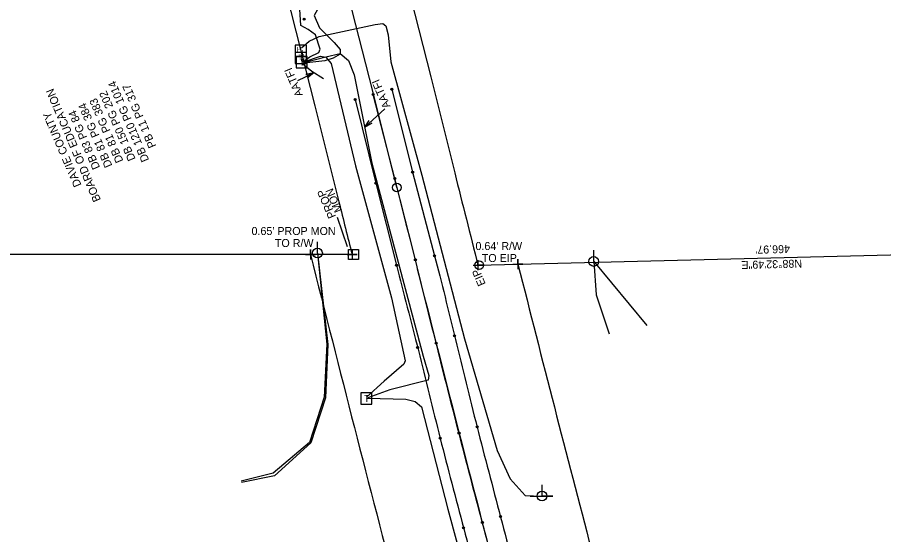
# Model space of a CAD drawing. Extents: x 1550153 to 1552579, y 809637 to 812160.
# Drawn here: x 1551459.6 to 1551894.8, y 811136.9 to 811396.7 of the extents above; entities that cross this region are included whole.
import ezdxf

# ---------------------------------------------------------------- set-up
doc = ezdxf.new("R2010")
doc.units = 0
for name, color, linetype in [('Default', 7, 'Continuous'), ('E_NCDOT_Horizontal_Alignment', 7, 'Continuous'), ('E_NCDOT_Horizontal_Alignment_Curve', 7, 'Continuous'), ('E_NCDOT_Horizontal_Alignment_Tick_Label', 7, 'Continuous'), ('Exist DTM Crownline', 7, 'Continuous'), ('Exist Property Corner CELL', 7, 'Continuous'), ('Exist Property Iron Pin CELL', 7, 'Continuous'), ('Exist Property Iron Pin Text', 7, 'Continuous'), ('Exist Property Line', 7, 'Continuous'), ('Exist Property Line Text', 7, 'Continuous'), ('Exist Property Monument CELL', 7, 'Continuous'), ('Exist Property Monument Leader', 7, 'Continuous'), ('Exist Property Monument Text', 7, 'Continuous'), ('Exist Property Text', 7, 'Continuous'), ('Exist Right of Way Line', 7, 'Continuous'), ('Exist Roads EOP', 7, 'Continuous'), ('Exist Utilities Power Joint Use Telephone CELL', 7, 'Continuous'), ('Exist Utilities Power Pole CELL', 7, 'Continuous'), ('Exist Utilities Power UG Cable SUE LOS B', 7, 'Continuous'), ('Exist Utilities Telephone Hand Hole CELL', 7, 'Continuous'), ('Exist Utilities Telephone Pedestal CELL', 7, 'Continuous'), ('Exist Utilities Telephone Text', 7, 'Continuous'), ('Exist Utilities Telephone UG Cable SUE LOS B', 7, 'Continuous'), ('Exist Utilities Telephone UG FO SUE LOS B', 7, 'Continuous')]:
    doc.layers.add(name, color=color, linetype=linetype)

# ---------------------------------------------------------------- blocks, each defined once
blk = doc.blocks.new('SurveyPointCell')
at = {"layer": 'Default'}
for p, q in [((-0.5, 0), (0.5, 0)), ((0, -0.5), (0, 0.5))]:
    blk.add_line(p, q, dxfattribs=at)
blk.add_circle((0, 0), 0.5, dxfattribs=at)

msp = doc.modelspace()

# ---------------------------------------------------------------- linework, layer by layer
at = {"layer": 'Default'}
msp.add_line((1551650.26, 811311.28), (1551638.16, 811359.58), dxfattribs=at)
msp.add_line((1551650.26, 811311.28), (1551638.16, 811359.58), dxfattribs=at)
msp.add_line((1551650.26, 811311.28), (1551638.16, 811359.58), dxfattribs=at)
at = {"layer": 'E_NCDOT_Horizontal_Alignment'}
for p, q in [((1551638.16, 811359.58), (1551604.47, 811492.11)), ((1551650.26, 811311.28), (1551638.16, 811359.58))]:
    msp.add_line(p, q, dxfattribs=at)
for radius in [2.2, 0.0707]:
    msp.add_circle((1551650.26, 811311.28), radius, dxfattribs=at)
at = {"layer": 'E_NCDOT_Horizontal_Alignment_Curve'}
msp.add_arc((1571051.3, 816169.19), 20000, 194.057496, 194.632887, dxfattribs=at)
msp.add_arc((1571051.3, 816169.19), 20000, 194.057496, 194.632887, dxfattribs=at)
at = {"layer": 'E_NCDOT_Horizontal_Alignment_Tick_Label'}
msp.add_line((1551650.26, 811311.28), (1551638.16, 811359.58), dxfattribs=at)
at = {"layer": 'Exist DTM Crownline'}
for p, q in [((1551649.24, 811315.83), (1551638.36, 811358.03)), ((1551649.24, 811315.83), (1551638.36, 811358.03)), ((1551659.56, 811274.89), (1551649.24, 811315.83)), ((1551659.56, 811274.89), (1551649.24, 811315.83))]:
    msp.add_line(p, q, dxfattribs=at)
msp.add_open_spline([(1551774.27, 810871.88), (1551769.96, 810884.28), (1551760.75, 810912.22), (1551745.66, 810955.91), (1551731.5, 811003.54), (1551718, 811050.78), (1551705.43, 811097.26), (1551693.24, 811142.67), (1551681.43, 811187.98), (1551670.2, 811231.95), (1551663.06, 811260.98), (1551659.56, 811274.89)], degree=3, dxfattribs=at)
msp.add_open_spline([(1551774.27, 810871.88), (1551769.96, 810884.28), (1551760.75, 810912.22), (1551745.66, 810955.91), (1551731.5, 811003.54), (1551718, 811050.78), (1551705.43, 811097.26), (1551693.24, 811142.67), (1551681.43, 811187.98), (1551670.2, 811231.95), (1551663.06, 811260.98), (1551659.56, 811274.89)], degree=3, dxfattribs=at)
at = {"layer": 'Exist Property Corner CELL'}
for p, q in [((1551606.86, 811277.65), (1551606.86, 811277.65)), ((1551627.77, 811277.65), (1551627.77, 811277.65)), ((1551691.02, 811272.23), (1551691.02, 811272.23)), ((1551711.09, 811272.74), (1551711.09, 811272.74))]:
    msp.add_line(p, q, dxfattribs=at)
for points in [[(1551604.36, 811277.65), (1551609.36, 811277.65), (1551606.86, 811277.65), (1551606.86, 811280.15), (1551606.86, 811275.15)], [(1551625.27, 811277.65), (1551630.27, 811277.65), (1551627.77, 811277.65), (1551627.77, 811280.15), (1551627.77, 811275.15)], [(1551688.52, 811272.23), (1551693.52, 811272.23), (1551691.02, 811272.23), (1551691.02, 811274.73), (1551691.02, 811269.73)], [(1551708.59, 811272.74), (1551713.59, 811272.74), (1551711.09, 811272.74), (1551711.09, 811275.24), (1551711.09, 811270.24)]]:
    msp.add_lwpolyline(points, dxfattribs=at)
at = {"layer": 'Exist Property Iron Pin CELL'}
for radius in [2.2, 2.2, 0.0707, 0.0707]:
    msp.add_circle((1551691.66, 811272.25), radius, dxfattribs=at)
at = {"layer": 'Exist Property Line'}
for p, q in [((1551711.09, 811272.74), (1552177.91, 811284.58)), ((1551606.86, 811277.65), (1550155.29, 811277.65))]:
    msp.add_line(p, q, dxfattribs=at)
at = {"layer": 'Exist Property Monument CELL'}
msp.add_line((1551628.41, 811277.65), (1551628.41, 811277.65), dxfattribs=at)
msp.add_line((1551628.41, 811277.65), (1551628.41, 811277.65), dxfattribs=at)
msp.add_lwpolyline([(1551625.92, 811275.16), (1551625.92, 811280.15), (1551630.91, 811280.15), (1551630.91, 811275.16), (1551625.92, 811275.16)], dxfattribs=at)
msp.add_lwpolyline([(1551625.92, 811275.16), (1551625.92, 811280.15), (1551630.91, 811280.15), (1551630.91, 811275.16), (1551625.92, 811275.16)], dxfattribs=at)
at = {"layer": 'Exist Property Monument Leader'}
msp.add_line((1551625.48, 811281.54), (1551620.36, 811296.19), dxfattribs=at)
at = {"layer": 'Exist Right of Way Line'}
for p, q in [((1551627.77, 811277.65), (1551606.86, 811277.65)), ((1551691.02, 811272.23), (1551711.09, 811272.74))]:
    msp.add_line(p, q, dxfattribs=at)
for points in [[(1551633.36, 811500.25), (1551633.56, 811499.43), (1551667.25, 811366.92), (1551679.36, 811318.56)], [(1551575.15, 811485.71), (1551575.38, 811484.78), (1551609.07, 811352.24), (1551621.15, 811303.99)]]:
    msp.add_lwpolyline(points, dxfattribs=at)
for centre, radius, start, end in [((1571051.3, 816169.19), 19970, 194.057496, 194.194571), ((1571051.3, 816169.19), 20030, 194.057496, 194.135176), ((1571051.08, 816168.98), 20050, 194.120183, 194.632887), ((1571050.91, 816169.06), 19950, 194.207218, 194.632275)]:
    msp.add_arc(centre, radius, start, end, dxfattribs=at)
at = {"layer": 'Exist Roads EOP'}
for p, q in [((1551647.8, 811360.59), (1551658.19, 811318.94)), ((1551647.8, 811360.59), (1551658.19, 811318.94)), ((1551629.3, 811355.5), (1551639.73, 811313.5)), ((1551629.3, 811355.5), (1551639.73, 811313.5)), ((1551658.19, 811318.94), (1551669.23, 811277)), ((1551658.19, 811318.94), (1551669.23, 811277)), ((1551639.73, 811313.5), (1551650.09, 811272.18)), ((1551639.73, 811313.5), (1551650.09, 811272.18))]:
    msp.add_line(p, q, dxfattribs=at)
for points in [[(1551669.23, 811277), (1551672.74, 811263.65), (1551679.61, 811234.96), (1551690.37, 811191.22), (1551702.41, 811145.66), (1551714.33, 811100.03), (1551727, 811053.46), (1551740.47, 811006.5), (1551755.13, 810959.34), (1551769.1, 810915.85), (1551778.93, 810888.33), (1551783.17, 810876.09)], [(1551669.23, 811277), (1551672.74, 811263.65), (1551679.61, 811234.96), (1551690.37, 811191.22), (1551702.41, 811145.66), (1551714.33, 811100.03), (1551727, 811053.46), (1551740.47, 811006.5), (1551755.13, 810959.34), (1551769.1, 810915.85), (1551778.93, 810888.33), (1551783.17, 810876.09)], [(1551650.09, 811272.18), (1551653.54, 811258.38), (1551661.25, 811229.54), (1551671.78, 811185.41), (1551683.85, 811140.03), (1551696.07, 811094.57), (1551708.62, 811047.91), (1551722.36, 811000.57), (1551736.98, 810952.93), (1551751.55, 810908.96), (1551760.88, 810880.93), (1551765.29, 810868.44)], [(1551650.09, 811272.18), (1551653.54, 811258.38), (1551661.25, 811229.54), (1551671.78, 811185.41), (1551683.85, 811140.03), (1551696.07, 811094.57), (1551708.62, 811047.91), (1551722.36, 811000.57), (1551736.98, 810952.93), (1551751.55, 810908.96), (1551760.88, 810880.93), (1551765.29, 810868.44)]]:
    msp.add_open_spline(points, degree=3, dxfattribs=at)
at = {"layer": 'Exist Utilities Power Joint Use Telephone CELL'}
msp.add_line((1551723.19, 811156.28), (1551723.19, 811156.28), dxfattribs=at)
msp.add_lwpolyline([(1551717.25, 811156.28), (1551728.59, 811156.24), (1551723.19, 811156.26), (1551723.19, 811161.9)], dxfattribs=at)
msp.add_circle((1551723.19, 811156.28), 2.45, dxfattribs=at)
at = {"layer": 'Exist Utilities Power Pole CELL'}
for p, q in [((1551610.39, 811278.35), (1551610.39, 811283.97)), ((1551749.18, 811274.1), (1551749.18, 811279.72)), ((1551610.39, 811278.35), (1551610.39, 811278.35)), ((1551749.18, 811274.1), (1551749.18, 811274.1))]:
    msp.add_line(p, q, dxfattribs=at)
for centre in [(1551610.39, 811278.35), (1551749.18, 811274.1)]:
    msp.add_circle(centre, 2.45, dxfattribs=at)
at = {"layer": 'Exist Utilities Power UG Cable SUE LOS B'}
for points in [[(1551610.38, 811278.35), (1551615.03, 811232.52), (1551613.73, 811205.91), (1551606.36, 811183.25), (1551588.07, 811167.69), (1551572.1, 811163.7)], [(1551610.39, 811278.35), (1551615.66, 811232.45), (1551614.45, 811205.63), (1551606.97, 811182.99), (1551588.76, 811166.39), (1551572.29, 811163.07)], [(1551749.17, 811274.1), (1551750.46, 811257.3), (1551756.99, 811237.84)], [(1551749.17, 811274.1), (1551775.84, 811242.01)]]:
    msp.add_lwpolyline(points, dxfattribs=at)
at = {"layer": 'Exist Utilities Telephone Hand Hole CELL'}
for p, q in [((1551599.19, 811382.74), (1551599.19, 811377.02)), ((1551604.92, 811382.74), (1551599.19, 811382.74)), ((1551602.05, 811379.88), (1551602.05, 811379.88)), ((1551604.92, 811377.02), (1551604.92, 811382.74)), ((1551599.19, 811377.02), (1551604.92, 811377.02))]:
    msp.add_line(p, q, dxfattribs=at)
at = {"layer": 'Exist Utilities Telephone Pedestal CELL'}
for p, q in [((1551601.97, 811376.33), (1551601.97, 811376.33)), ((1551602.39, 811374.26), (1551602.39, 811374.26)), ((1551634.9, 811205.29), (1551634.9, 811205.29))]:
    msp.add_line(p, q, dxfattribs=at)
for points in [[(1551599.25, 811373.5), (1551604.84, 811373.5), (1551604.84, 811379.09), (1551599.25, 811379.09), (1551599.25, 811373.5)], [(1551599.66, 811371.43), (1551605.26, 811371.43), (1551605.26, 811377.02), (1551599.66, 811377.02), (1551599.66, 811371.43)], [(1551632.17, 811202.47), (1551637.77, 811202.47), (1551637.77, 811208.06), (1551632.17, 811208.06), (1551632.17, 811202.47)]]:
    msp.add_lwpolyline(points, dxfattribs=at)
at = {"layer": 'Exist Utilities Telephone Text'}
for points in [[(1551600.52, 811365.04), (1551608.6, 811368.93), (1551604.54, 811368.09), (1551608.6, 811368.93), (1551605.41, 811366.28)], [(1551644.21, 811350.79), (1551634.13, 811341.55), (1551637.77, 811343.52), (1551634.13, 811341.55), (1551636.41, 811345)]]:
    msp.add_lwpolyline(points, dxfattribs=at)
at = {"layer": 'Exist Utilities Telephone UG Cable SUE LOS B'}
for points in [[(1551545.22, 811706.56), (1551568.37, 811609.79), (1551588, 811531.44), (1551606.27, 811452.93), (1551615.14, 811412.25), (1551613.21, 811406), (1551608.7, 811397.66), (1551611.45, 811391.52), (1551618.85, 811384.02), (1551621.83, 811380.6), (1551621.74, 811378.31), (1551618.28, 811376.25), (1551614.11, 811374.91), (1551603.55, 811373.65)], [(1551603.05, 811374.46), (1551606.52, 811376.87), (1551611, 811379.06), (1551611.78, 811380.7), (1551609.42, 811387.99), (1551605.7, 811390.64), (1551602.03, 811392.68), (1551601.58, 811400.81), (1551604.98, 811407.57), (1551605.14, 811413.37), (1551601.39, 811432.74), (1551598.88, 811434.08), (1551590.03, 811432.32)], [(1551603.47, 811374.33), (1551611.96, 811377.17), (1551614.58, 811376.75), (1551617.19, 811373.56), (1551629.5, 811322.12), (1551647.52, 811255.85), (1551654.41, 811224.24), (1551653.81, 811222.52), (1551643.81, 811214.04), (1551635.05, 811206.01)], [(1551603.59, 811374), (1551614.59, 811376.88), (1551621.72, 811378.56), (1551626.04, 811375.1), (1551628.85, 811367.88), (1551637.74, 811323.5), (1551663.4, 811226.58), (1551666.26, 811216.87), (1551665.95, 811214.46), (1551646.79, 811209.62), (1551635.64, 811205.53)], [(1551603.04, 811373.31), (1551607.52, 811369.75), (1551613.4, 811365.98)], [(1551635.47, 811205.41), (1551654.84, 811204.95), (1551659.43, 811203.7), (1551662.57, 811201.11), (1551675.9, 811149.68), (1551694.16, 811082.62), (1551715.46, 811009.19), (1551741.91, 810920.73), (1551757.61, 810876.2), (1551761.94, 810865.34), (1551769.04, 810860.85), (1551770.5, 810856.61)]]:
    msp.add_lwpolyline(points, dxfattribs=at)
at = {"layer": 'Exist Utilities Telephone UG FO SUE LOS B'}
for points in [[(1551602.44, 811381.48), (1551606.27, 811384.82), (1551611.26, 811387.07), (1551639.37, 811393.13), (1551643.29, 811393.6), (1551644.68, 811392.39), (1551645.96, 811387.93), (1551647.24, 811374.44), (1551662.83, 811317.5), (1551684.32, 811235.29), (1551700.68, 811179.2), (1551707.25, 811164.99), (1551714.69, 811156.53), (1551723.19, 811156.29)], [(1551603.14, 811378.1), (1551602.92, 811377.03), (1551602.58, 811376.35)]]:
    msp.add_lwpolyline(points, dxfattribs=at)

# ---------------------------------------------------------------- block references
at = {"layer": 'Default'}
for p in [(1551603.73, 811395.76), (1551603.73, 811395.76), (1551638.36, 811358.03), (1551638.36, 811358.03), (1551647.8, 811360.59), (1551647.8, 811360.59), (1551629.3, 811355.5), (1551629.3, 811355.5), (1551658.19, 811318.94), (1551658.19, 811318.94), (1551639.73, 811313.5), (1551639.73, 811313.5), (1551649.24, 811315.83), (1551649.24, 811315.83), (1551659.56, 811274.89), (1551659.56, 811274.89), (1551669.23, 811277), (1551669.23, 811277), (1551650.09, 811272.18), (1551650.09, 811272.18), (1551679.2, 811236.82), (1551679.2, 811236.82), (1551660.71, 811230.87), (1551660.71, 811230.87), (1551669.97, 811233.13), (1551669.97, 811233.13), (1551681.49, 811187.93), (1551681.49, 811187.93), (1551690.54, 811191.11), (1551690.54, 811191.11), (1551672, 811185.35), (1551672, 811185.35), (1551702.31, 811145.96), (1551702.31, 811145.96), (1551683.8, 811140.31), (1551683.8, 811140.31), (1551693.21, 811143), (1551693.21, 811143)]:
    msp.add_blockref('SurveyPointCell', p, dxfattribs=at)

# ---------------------------------------------------------------- texts
at = {"layer": 'Exist Property Iron Pin Text'}
msp.add_text('EIP', height=4.02, rotation=113.1736, dxfattribs=at).set_placement((1551694.97, 811262.79))
at = {"layer": 'Exist Property Line Text'}
for s, p in [("0.65' PROP MON", (1551577.26, 811287.4)), ('TO R/W', (1551588.99, 811281.37)), ("0.64' R/W", (1551689.76, 811279.86)), ('TO EIP', (1551692.93, 811273.83))]:
    msp.add_text(s, height=4.02, dxfattribs=at).set_placement(p)
for s, p in [("466.97'", (1551847.71, 811282.41)), ('N88°32\'49"E', (1551853.77, 811275.1))]:
    msp.add_text(s, height=4.02, rotation=181.453, dxfattribs=at).set_placement(p)
at = {"layer": 'Exist Property Monument Text'}
for s, p in [('PROP', (1551619.75, 811296.74)), ('MON', (1551622.88, 811299.73))]:
    msp.add_text(s, height=4.02, rotation=113.1736, dxfattribs=at).set_placement(p)
at = {"layer": 'Exist Property Text'}
for s, p in [('DB 1210 PG 1014', (1551525.88, 811325.09)), ('PB 11 PG 317', (1551529.44, 811332.1)), ('BOARD OF EDUCATION', (1551501.66, 811305.05)), ('DB 150 PG 202', (1551519.1, 811325.6)), ('DB 81 PG 384', (1551507.4, 811322.28)), ('DB 81 PG 383', (1551512.95, 811324.65)), ('DB 83 PG 84', (1551501.25, 811321.34)), ('DAVIE COUNTY', (1551491.9, 811312.52))]:
    msp.add_text(s, height=4.02, rotation=113.1736, dxfattribs=at).set_placement(p)
at = {"layer": 'Exist Utilities Telephone Hand Hole CELL'}
for p in [(1551599.97, 811379.29), (1551602.54, 811377.82)]:
    msp.add_text('H', height=2.5, dxfattribs=at).set_placement(p)
at = {"layer": 'Exist Utilities Telephone Pedestal CELL'}
for p in [(1551600.84, 811374.61), (1551601.26, 811372.54), (1551633.77, 811203.58)]:
    msp.add_text('T', height=3.42, dxfattribs=at).set_placement(p)
at = {"layer": 'Exist Utilities Telephone Text'}
for p in [(1551603.23, 811357.83), (1551647.16, 811352.02)]:
    msp.add_text('AATFI', height=4.02, rotation=113.1736, dxfattribs=at).set_placement(p)

doc.saveas('drawing.dxf')
